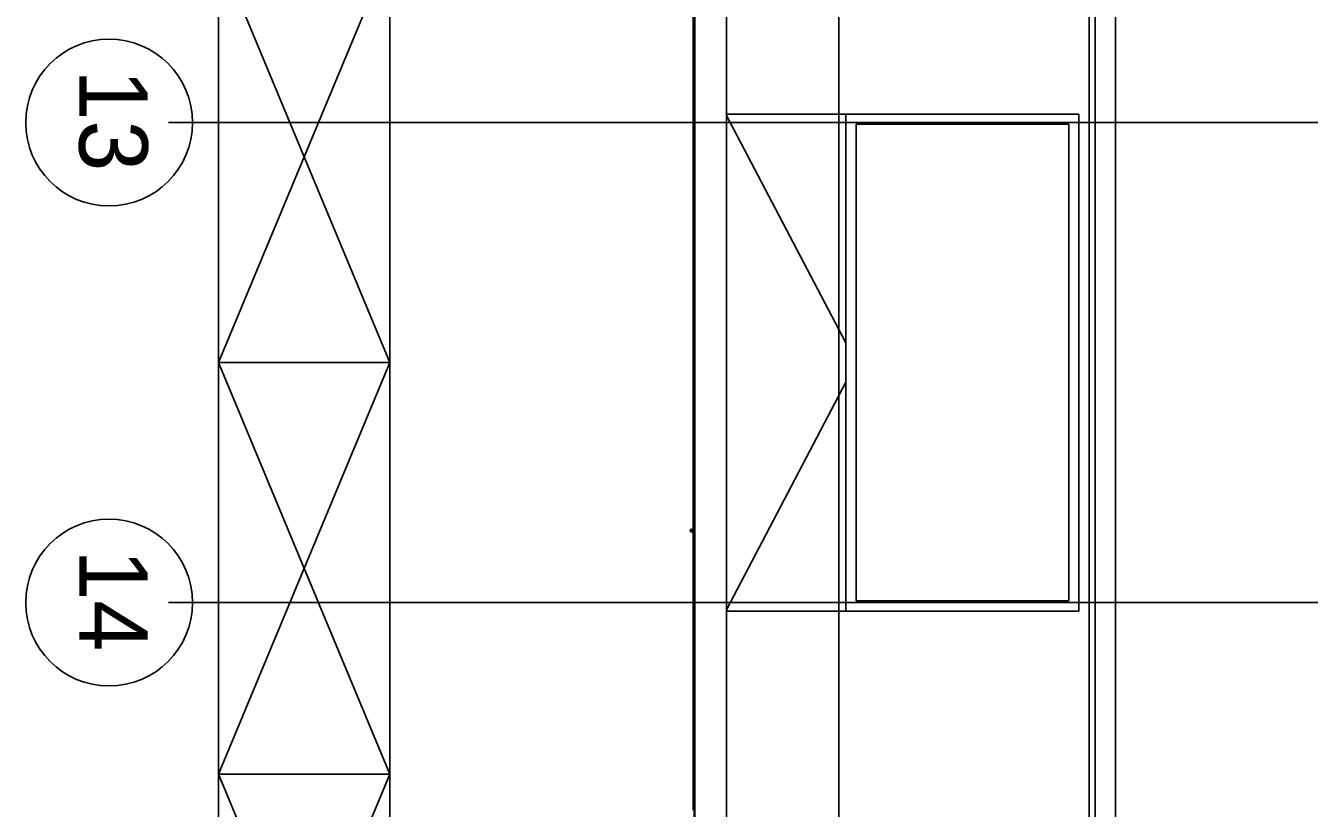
# Model space of a CAD drawing. Extents: x -264165 to -263575, y -1242333 to -1242036.
# Drawn here: x -263923.9 to -263905.18, y -1242170.88 to -1242159.47 of the extents above; entities that cross this region are included whole.
import ezdxf

# ---------------------------------------------------------------- set-up
doc = ezdxf.new("R2010")
doc.units = 0
doc.layers.add('KFA_HESCON_OSI_STAVBY', color=7, linetype='Continuous')
doc.layers.add('KFA_SITUACIA_DRS_VYTYCOVAK_SEDA', color=7, linetype='Continuous')

msp = doc.modelspace()

# ---------------------------------------------------------------- linework, layer by layer
at = {"layer": 'KFA_HESCON_OSI_STAVBY'}
for p, q in [((-263908.393, -1242080.447), (-263908.393, -1242248.737)), ((-263787.486, -1242160.882), (-263921.823, -1242160.882)), ((-263920.885, -1242160.882), (-263905.505, -1242160.882)), ((-263787.486, -1242167.882), (-263921.823, -1242167.882)), ((-263920.885, -1242167.882), (-263905.505, -1242167.882))]:
    msp.add_line(p, q, dxfattribs=at)
for centre in [(-263922.688, -1242160.882), (-263922.688, -1242167.882)]:
    msp.add_circle(centre, 1.216, dxfattribs=at)
at = {"layer": 'KFA_SITUACIA_DRS_VYTYCOVAK_SEDA'}
for p, q in [((-263921.093, -1242087.308), (-263921.093, -1242241.458)), ((-263912.043, -1242228.625), (-263912.043, -1242100.14)), ((-263914.153, -1242132.422), (-263914.153, -1242196.342)), ((-263914.153, -1242132.422), (-263914.153, -1242196.342)), ((-263914.143, -1242196.333), (-263914.143, -1242132.433)), ((-263913.683, -1242132.892), (-263913.683, -1242195.872)), ((-263913.683, -1242132.892), (-263913.683, -1242195.872)), ((-263908.308, -1242135.882), (-263908.308, -1242192.882)), ((-263908.308, -1242135.882), (-263908.308, -1242192.882)), ((-263908.008, -1242192.882), (-263908.008, -1242135.882)), ((-263908.008, -1242192.882), (-263908.008, -1242135.882)), ((-263918.593, -1242141.207), (-263918.593, -1242187.557)), ((-263921.093, -1242158.382), (-263918.593, -1242164.382)), ((-263921.093, -1242164.382), (-263918.593, -1242158.382)), ((-263914.168, -1242158.907), (-263914.168, -1242159.857)), ((-263914.168, -1242158.907), (-263914.168, -1242159.857)), ((-263914.168, -1242159.907), (-263914.168, -1242159.857)), ((-263914.168, -1242159.907), (-263914.168, -1242159.857)), ((-263914.168, -1242159.907), (-263914.168, -1242160.857)), ((-263914.168, -1242159.907), (-263914.168, -1242160.857)), ((-263914.168, -1242160.907), (-263914.168, -1242160.857)), ((-263914.168, -1242160.907), (-263914.168, -1242160.857)), ((-263911.943, -1242160.757), (-263913.683, -1242160.757)), ((-263911.943, -1242160.757), (-263913.683, -1242160.757)), ((-263913.683, -1242160.776), (-263911.943, -1242164.096)), ((-263913.683, -1242160.776), (-263911.943, -1242164.096)), ((-263911.943, -1242160.757), (-263911.793, -1242160.757)), ((-263911.943, -1242160.757), (-263911.793, -1242160.757)), ((-263911.943, -1242165.557), (-263911.943, -1242160.757)), ((-263911.943, -1242165.557), (-263911.943, -1242160.757)), ((-263911.793, -1242160.757), (-263908.593, -1242160.757)), ((-263911.793, -1242160.757), (-263908.593, -1242160.757)), ((-263908.593, -1242160.757), (-263908.543, -1242160.757)), ((-263908.593, -1242160.757), (-263908.543, -1242160.757)), ((-263908.543, -1242160.757), (-263908.543, -1242167.857)), ((-263908.543, -1242160.757), (-263908.543, -1242167.857)), ((-263914.168, -1242160.907), (-263914.168, -1242161.857)), ((-263914.168, -1242160.907), (-263914.168, -1242161.857)), ((-263908.693, -1242160.907), (-263911.793, -1242160.907)), ((-263908.693, -1242160.907), (-263911.793, -1242160.907)), ((-263911.793, -1242160.907), (-263911.793, -1242165.557)), ((-263911.793, -1242160.907), (-263911.793, -1242165.557)), ((-263908.693, -1242167.857), (-263908.693, -1242160.907)), ((-263908.693, -1242167.857), (-263908.693, -1242160.907)), ((-263914.168, -1242161.907), (-263914.168, -1242161.857)), ((-263914.168, -1242161.907), (-263914.168, -1242161.857)), ((-263914.168, -1242161.907), (-263914.168, -1242162.857)), ((-263914.168, -1242161.907), (-263914.168, -1242162.857)), ((-263914.168, -1242162.907), (-263914.168, -1242162.857)), ((-263914.168, -1242162.907), (-263914.168, -1242162.857)), ((-263914.168, -1242162.907), (-263914.168, -1242163.857)), ((-263914.168, -1242162.907), (-263914.168, -1242163.857)), ((-263914.168, -1242163.907), (-263914.168, -1242163.857)), ((-263914.168, -1242163.907), (-263914.168, -1242163.857)), ((-263914.168, -1242163.907), (-263914.168, -1242164.857)), ((-263914.168, -1242163.907), (-263914.168, -1242164.857)), ((-263921.093, -1242164.382), (-263918.593, -1242164.382)), ((-263921.093, -1242164.382), (-263918.593, -1242170.382)), ((-263921.093, -1242170.382), (-263918.593, -1242164.382)), ((-263911.943, -1242164.669), (-263913.683, -1242167.988)), ((-263911.943, -1242164.669), (-263913.683, -1242167.988)), ((-263914.168, -1242164.907), (-263914.168, -1242164.857)), ((-263914.168, -1242164.907), (-263914.168, -1242164.857)), ((-263914.168, -1242164.907), (-263914.168, -1242165.857)), ((-263914.168, -1242164.907), (-263914.168, -1242165.857)), ((-263911.943, -1242168.007), (-263911.943, -1242165.557)), ((-263911.943, -1242168.007), (-263911.943, -1242165.557)), ((-263911.793, -1242165.557), (-263911.793, -1242167.857)), ((-263911.793, -1242165.557), (-263911.793, -1242167.857)), ((-263914.168, -1242165.907), (-263914.168, -1242165.857)), ((-263914.168, -1242165.907), (-263914.168, -1242165.857)), ((-263914.168, -1242165.907), (-263914.168, -1242166.857)), ((-263914.168, -1242165.907), (-263914.168, -1242166.857)), ((-263914.213, -1242166.832), (-263914.21, -1242166.822)), ((-263914.213, -1242166.832), (-263914.21, -1242166.822)), ((-263914.21, -1242166.842), (-263914.213, -1242166.832)), ((-263914.21, -1242166.842), (-263914.213, -1242166.832)), ((-263914.21, -1242166.822), (-263914.203, -1242166.815)), ((-263914.21, -1242166.822), (-263914.203, -1242166.815)), ((-263914.21, -1242166.824), (-263914.21, -1242166.822)), ((-263914.21, -1242166.824), (-263914.21, -1242166.822)), ((-263914.21, -1242166.827), (-263914.21, -1242166.824)), ((-263914.21, -1242166.827), (-263914.21, -1242166.824)), ((-263914.21, -1242166.832), (-263914.21, -1242166.827)), ((-263914.21, -1242166.832), (-263914.21, -1242166.827)), ((-263914.21, -1242166.837), (-263914.21, -1242166.832)), ((-263914.21, -1242166.837), (-263914.21, -1242166.832)), ((-263914.21, -1242166.841), (-263914.21, -1242166.837)), ((-263914.21, -1242166.841), (-263914.21, -1242166.837)), ((-263914.21, -1242166.842), (-263914.21, -1242166.841)), ((-263914.21, -1242166.842), (-263914.21, -1242166.841)), ((-263914.203, -1242166.85), (-263914.21, -1242166.842)), ((-263914.203, -1242166.85), (-263914.21, -1242166.842)), ((-263914.203, -1242166.815), (-263914.193, -1242166.812)), ((-263914.203, -1242166.815), (-263914.193, -1242166.812)), ((-263914.203, -1242166.817), (-263914.203, -1242166.815)), ((-263914.203, -1242166.817), (-263914.203, -1242166.815)), ((-263914.203, -1242166.817), (-263914.193, -1242166.815)), ((-263914.203, -1242166.817), (-263914.193, -1242166.815)), ((-263914.203, -1242166.824), (-263914.203, -1242166.817)), ((-263914.203, -1242166.824), (-263914.203, -1242166.817)), ((-263914.203, -1242166.824), (-263914.193, -1242166.822)), ((-263914.203, -1242166.824), (-263914.193, -1242166.822)), ((-263914.203, -1242166.832), (-263914.203, -1242166.824)), ((-263914.203, -1242166.832), (-263914.203, -1242166.824)), ((-263914.203, -1242166.841), (-263914.203, -1242166.832)), ((-263914.203, -1242166.841), (-263914.203, -1242166.832)), ((-263914.203, -1242166.832), (-263914.193, -1242166.832)), ((-263914.203, -1242166.832), (-263914.193, -1242166.832)), ((-263914.203, -1242166.841), (-263914.193, -1242166.842)), ((-263914.203, -1242166.841), (-263914.193, -1242166.842)), ((-263914.203, -1242166.847), (-263914.203, -1242166.841)), ((-263914.203, -1242166.847), (-263914.203, -1242166.841)), ((-263914.203, -1242166.85), (-263914.203, -1242166.847)), ((-263914.203, -1242166.85), (-263914.203, -1242166.847)), ((-263914.203, -1242166.847), (-263914.193, -1242166.85)), ((-263914.203, -1242166.847), (-263914.193, -1242166.85)), ((-263914.193, -1242166.852), (-263914.203, -1242166.85)), ((-263914.193, -1242166.852), (-263914.203, -1242166.85)), ((-263914.193, -1242166.812), (-263914.183, -1242166.815)), ((-263914.193, -1242166.812), (-263914.183, -1242166.815)), ((-263914.193, -1242166.812), (-263914.193, -1242166.815)), ((-263914.193, -1242166.812), (-263914.193, -1242166.815)), ((-263914.193, -1242166.815), (-263914.183, -1242166.817)), ((-263914.193, -1242166.815), (-263914.183, -1242166.817)), ((-263914.193, -1242166.815), (-263914.193, -1242166.822)), ((-263914.193, -1242166.815), (-263914.193, -1242166.822)), ((-263914.193, -1242166.822), (-263914.193, -1242166.832)), ((-263914.193, -1242166.822), (-263914.193, -1242166.832)), ((-263914.193, -1242166.822), (-263914.183, -1242166.824)), ((-263914.193, -1242166.822), (-263914.183, -1242166.824)), ((-263914.193, -1242166.832), (-263914.193, -1242166.842)), ((-263914.193, -1242166.832), (-263914.193, -1242166.842)), ((-263914.193, -1242166.832), (-263914.183, -1242166.832)), ((-263914.193, -1242166.832), (-263914.183, -1242166.832)), ((-263914.193, -1242166.842), (-263914.183, -1242166.841)), ((-263914.193, -1242166.842), (-263914.183, -1242166.841)), ((-263914.193, -1242166.842), (-263914.193, -1242166.85)), ((-263914.193, -1242166.842), (-263914.193, -1242166.85)), ((-263914.193, -1242166.85), (-263914.183, -1242166.847)), ((-263914.193, -1242166.85), (-263914.183, -1242166.847)), ((-263914.193, -1242166.85), (-263914.193, -1242166.852)), ((-263914.193, -1242166.85), (-263914.193, -1242166.852)), ((-263914.183, -1242166.85), (-263914.193, -1242166.852)), ((-263914.183, -1242166.85), (-263914.193, -1242166.852)), ((-263914.183, -1242166.815), (-263914.176, -1242166.822)), ((-263914.183, -1242166.815), (-263914.176, -1242166.822)), ((-263914.183, -1242166.815), (-263914.183, -1242166.817)), ((-263914.183, -1242166.815), (-263914.183, -1242166.817)), ((-263914.183, -1242166.817), (-263914.183, -1242166.824)), ((-263914.183, -1242166.817), (-263914.183, -1242166.824)), ((-263914.183, -1242166.824), (-263914.183, -1242166.832)), ((-263914.183, -1242166.824), (-263914.183, -1242166.832)), ((-263914.183, -1242166.832), (-263914.183, -1242166.841)), ((-263914.183, -1242166.832), (-263914.183, -1242166.841)), ((-263914.183, -1242166.841), (-263914.183, -1242166.847)), ((-263914.183, -1242166.841), (-263914.183, -1242166.847)), ((-263914.176, -1242166.842), (-263914.183, -1242166.85)), ((-263914.176, -1242166.842), (-263914.183, -1242166.85)), ((-263914.183, -1242166.847), (-263914.183, -1242166.85)), ((-263914.183, -1242166.847), (-263914.183, -1242166.85)), ((-263914.176, -1242166.822), (-263914.168, -1242166.822)), ((-263914.176, -1242166.822), (-263914.168, -1242166.822)), ((-263914.176, -1242166.822), (-263914.176, -1242166.824)), ((-263914.176, -1242166.822), (-263914.176, -1242166.824)), ((-263914.176, -1242166.824), (-263914.168, -1242166.824)), ((-263914.176, -1242166.824), (-263914.168, -1242166.824)), ((-263914.176, -1242166.824), (-263914.176, -1242166.827)), ((-263914.176, -1242166.824), (-263914.176, -1242166.827)), ((-263914.176, -1242166.827), (-263914.168, -1242166.827)), ((-263914.176, -1242166.827), (-263914.168, -1242166.827)), ((-263914.176, -1242166.827), (-263914.176, -1242166.832)), ((-263914.176, -1242166.827), (-263914.176, -1242166.832)), ((-263914.176, -1242166.832), (-263914.168, -1242166.832)), ((-263914.176, -1242166.832), (-263914.168, -1242166.832)), ((-263914.176, -1242166.832), (-263914.176, -1242166.837)), ((-263914.176, -1242166.832), (-263914.176, -1242166.837)), ((-263914.176, -1242166.837), (-263914.168, -1242166.837)), ((-263914.176, -1242166.837), (-263914.168, -1242166.837)), ((-263914.176, -1242166.837), (-263914.176, -1242166.841)), ((-263914.176, -1242166.837), (-263914.176, -1242166.841)), ((-263914.176, -1242166.841), (-263914.168, -1242166.841)), ((-263914.176, -1242166.841), (-263914.168, -1242166.841)), ((-263914.176, -1242166.841), (-263914.176, -1242166.842)), ((-263914.176, -1242166.841), (-263914.176, -1242166.842)), ((-263914.176, -1242166.842), (-263914.168, -1242166.842)), ((-263914.176, -1242166.842), (-263914.168, -1242166.842)), ((-263914.168, -1242166.907), (-263914.168, -1242166.857)), ((-263914.168, -1242166.907), (-263914.168, -1242166.857)), ((-263914.168, -1242166.907), (-263914.168, -1242167.857)), ((-263914.168, -1242166.907), (-263914.168, -1242167.857)), ((-263914.168, -1242167.907), (-263914.168, -1242167.857)), ((-263914.168, -1242167.907), (-263914.168, -1242167.857)), ((-263914.168, -1242167.907), (-263914.168, -1242168.857)), ((-263914.168, -1242167.907), (-263914.168, -1242168.857)), ((-263914.168, -1242167.907), (-263914.168, -1242168.857)), ((-263914.168, -1242167.907), (-263914.168, -1242168.857)), ((-263913.683, -1242168.007), (-263911.943, -1242168.007)), ((-263913.683, -1242168.007), (-263911.943, -1242168.007)), ((-263911.793, -1242168.007), (-263911.943, -1242168.007)), ((-263911.793, -1242168.007), (-263911.943, -1242168.007)), ((-263911.793, -1242167.857), (-263908.693, -1242167.857)), ((-263911.793, -1242167.857), (-263908.693, -1242167.857)), ((-263908.543, -1242168.007), (-263911.793, -1242168.007)), ((-263908.543, -1242168.007), (-263911.793, -1242168.007)), ((-263908.543, -1242167.857), (-263908.543, -1242168.007)), ((-263908.543, -1242167.857), (-263908.543, -1242168.007)), ((-263914.168, -1242168.907), (-263914.168, -1242168.857)), ((-263914.168, -1242168.907), (-263914.168, -1242168.857)), ((-263914.168, -1242168.907), (-263914.168, -1242169.857)), ((-263914.168, -1242168.907), (-263914.168, -1242169.857)), ((-263914.168, -1242169.907), (-263914.168, -1242169.857)), ((-263914.168, -1242169.907), (-263914.168, -1242169.857)), ((-263914.168, -1242169.907), (-263914.168, -1242170.857)), ((-263914.168, -1242169.907), (-263914.168, -1242170.857)), ((-263921.093, -1242170.382), (-263918.593, -1242170.382)), ((-263921.093, -1242170.382), (-263918.593, -1242176.382)), ((-263921.093, -1242176.382), (-263918.593, -1242170.382)), ((-263914.168, -1242170.907), (-263914.168, -1242170.857)), ((-263914.168, -1242170.907), (-263914.168, -1242170.857))]:
    msp.add_line(p, q, dxfattribs=at)

# ---------------------------------------------------------------- texts
at = {"layer": 'KFA_HESCON_OSI_STAVBY'}
for s, p in [('13', (-263923.123, -1242160.105)), ('14', (-263923.123, -1242167.105))]:
    msp.add_text(s, height=1, rotation=270, dxfattribs=at).set_placement(p)

doc.saveas('drawing.dxf')
